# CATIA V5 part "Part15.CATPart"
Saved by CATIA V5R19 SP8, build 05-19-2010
Part number: Pignon
Bounding box of the stored display mesh (mm): x 0 to 5, y 387.754 to 585.27, z -138.402 to 59.343
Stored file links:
  G:\EU_thinkMotion\CFAO_2010\MMS_groupe1\MMS_groupe1\OK\ppiault\piault\piault_cfao\Part15.CATPart
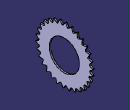
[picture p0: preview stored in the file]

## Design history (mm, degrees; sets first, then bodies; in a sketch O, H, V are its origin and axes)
Body1 (main body)
  Sketch1 on yz-plane, origin (0, 0, 0), H (0, 1, 0), V (0, 0, 1)
    circle A1 centre (486.5119, -39.5298) radius 52
    point P1 (486.5119, -39.5298)
    arc A2 centre (486.5119, -39.5298) radius 85 from (570.2939, -25.1915) to (571.4403, -43.0186) ccw
    point P2 (486.5119, -39.5298)
    line L1 (570.2939, -25.1915) -> (586.3058, -33.1122)
    point P4 (586.3058, -33.1122)
    line L2 (586.3058, -33.1122) -> (571.4403, -43.0186)
    radius A1 = 52
    radius A2 = 85
    distance P4 P2 = 100
    angle L1 L2 = 60
    concentricity: A2 P1
  Pad1: profile Sketch1, direction (1, 0, 0), length 5
  CircPattern1: of Pad1, instances 31, angular step 12, axis from end face of Pad1
  Fillet1: radius 3, on edge [face of CircPattern1 | face of CircPattern1] (x30)
  Fillet2: radius 1, on edge [face of CircPattern1 | face of CircPattern1] (x30)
